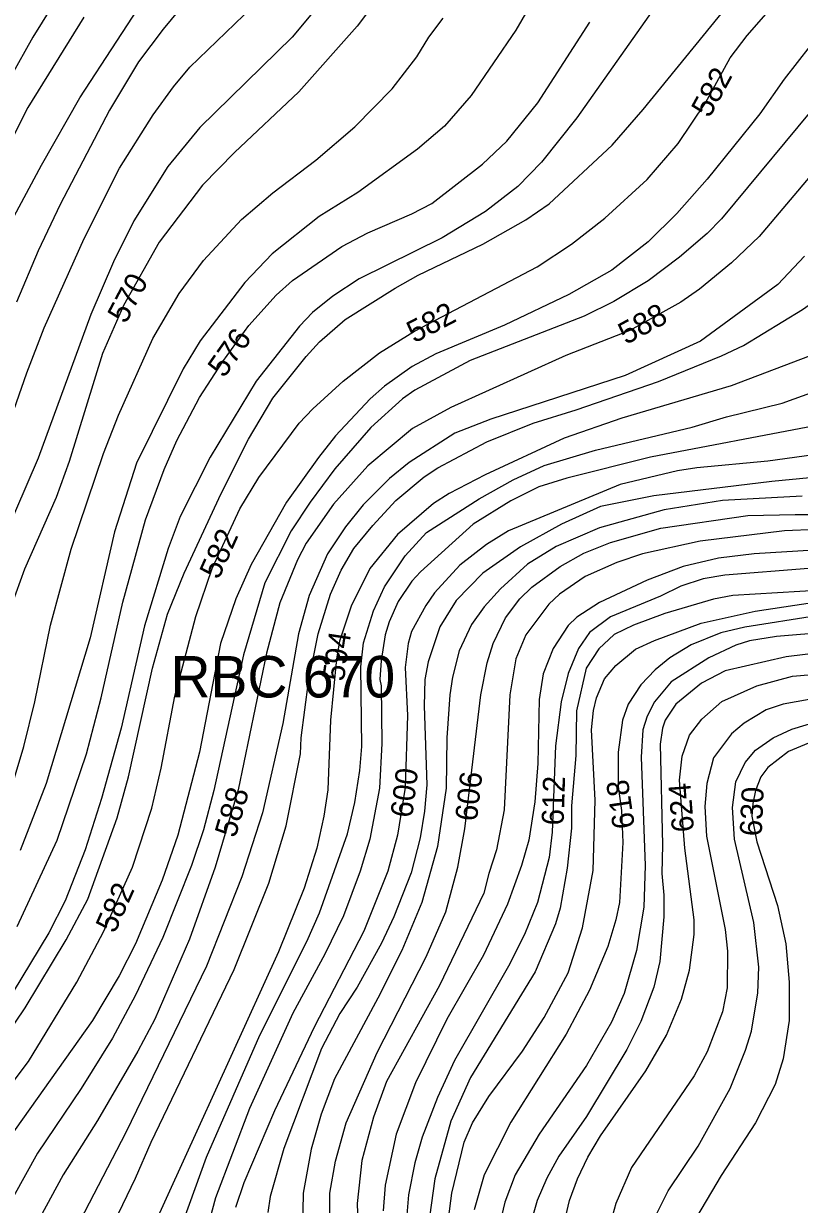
# Model space of a CAD drawing. Extents: x -709418 to -703832, y -1161719 to -1157826.
# Drawn here: x -709000.3 to -708719.1, y -1160771.9 to -1160344.3 of the extents above; entities that cross this region are included whole.
import ezdxf

# ---------------------------------------------------------------- set-up
doc = ezdxf.new("R2010")
doc.units = 0
for name, color, linetype in [('120_vrstevnice hlavní', 7, 'Continuous'), ('121_vrstevnice hlavní_popis', 7, 'Continuous'), ('122_vrstevnice základní', 7, 'Continuous'), ('605_RBC_návrh_popis', 7, 'Continuous')]:
    doc.layers.add(name, color=color, linetype=linetype)

msp = doc.modelspace()

# ---------------------------------------------------------------- linework, layer by layer
at = {"layer": '120_vrstevnice hlavní'}
for points in [[(-708869.72, -1160332.34), (-708879.41, -1160345.21), (-708900.53, -1160369.08), (-708923.82, -1160391.06), (-708935.39, -1160402.78), (-708951.15, -1160423.46), (-708964.03, -1160446.46), (-708971.69, -1160463.82), (-708983.7, -1160502.87), (-708988.47, -1160515.89), (-708999.9, -1160541.93), (-709004.67, -1160554.95)], [(-708953.61, -1160577.8), (-708948.11, -1160558.13), (-708942.04, -1160543.37), (-708928.73, -1160514.45), (-708918.75, -1160494.77), (-708909.93, -1160480.02), (-708897.92, -1160464.83), (-708893.01, -1160459.62), (-708883.75, -1160451.53), (-708865.67, -1160440.1), (-708857.28, -1160435.47), (-708833.85, -1160424.19), (-708818.22, -1160415.36), (-708809.84, -1160409.58), (-708786.98, -1160388.31), (-708775.7, -1160375.44), (-708744.89, -1160337.55)], [(-708978.49, -1160342.03), (-708998.74, -1160374.72), (-709009.3, -1160395.55)], [(-708717.26, -1160428.53), (-708726.95, -1160438.8), (-708755.02, -1160459.33), (-708782.24, -1160471.81), (-708830.95, -1160487.54), (-708843.97, -1160492.6), (-708860.6, -1160503.31), (-708867.69, -1160509.09), (-708877.24, -1160518.64), (-708883.6, -1160526.59), (-708890.11, -1160536.29), (-708896.77, -1160551.47), (-708900.67, -1160565.36), (-708906.31, -1160597.76), (-708913.69, -1160630.16), (-708921.21, -1160653.3), (-708933.94, -1160685.7), (-708963.16, -1160745.88), (-708984.85, -1160787.53)], [(-708704.24, -1160499.11), (-708730.57, -1160502.73), (-708756.32, -1160505.19), (-708763.26, -1160506.34), (-708784.09, -1160511.26), (-708824.59, -1160528.04), (-708832.54, -1160532.96), (-708842.23, -1160540.48), (-708851.35, -1160550.46), (-708854.53, -1160555.09), (-708859.74, -1160564.49), (-708860.9, -1160568.83), (-708862.05, -1160577.51), (-708861.18, -1160594.87), (-708862.05, -1160620.9), (-708864.8, -1160638.26), (-708868.27, -1160651.28), (-708876.95, -1160672.98), (-708895.03, -1160707.69), (-708909.35, -1160738.07), (-708920.49, -1160764.1), (-708923.53, -1160773.07)], [(-708440.12, -1160521.68), (-708459.8, -1160526.16), (-708478.31, -1160531.95), (-708502.32, -1160538.31), (-708531.83, -1160547.14), (-708566.25, -1160555.09), (-708587.93, -1160558.27), (-708616.59, -1160561.6), (-708630.48, -1160561.6), (-708658.54, -1160563.19), (-708688.05, -1160563.05), (-708727.39, -1160566.23), (-708737.22, -1160567.82), (-708742.14, -1160569.41), (-708751.98, -1160574.04), (-708765.57, -1160582.72)], [(-708713.79, -1160534.98), (-708735.49, -1160536.29), (-708748.51, -1160537.88), (-708761.23, -1160540.92), (-708774.25, -1160545.83), (-708791.61, -1160553.93), (-708799.85, -1160559.29), (-708802.89, -1160562.32), (-708808.39, -1160570.57), (-708812.01, -1160579.82), (-708813.45, -1160589.08), (-708813.89, -1160612.23), (-708815.04, -1160626.11), (-708817.21, -1160640), (-708819.82, -1160649.25), (-708824.88, -1160663.14), (-708833.56, -1160681.65), (-708846.86, -1160704.8), (-708858.29, -1160727.94), (-708865.23, -1160746.46), (-708869.28, -1160764.97), (-708870.01, -1160774.23)], [(-709026.37, -1160740.09), (-708999.75, -1160700.75), (-708984.85, -1160676.16), (-708977.04, -1160661.4), (-708966.34, -1160631.9), (-708962.29, -1160617.14), (-708953.61, -1160577.8)], [(-708765.57, -1160582.72), (-708771.65, -1160589.95), (-708774.25, -1160595.16), (-708775.84, -1160600.07), (-708776.42, -1160609.91), (-708774.98, -1160649.25), (-708775.56, -1160664.3), (-708778.16, -1160679.92), (-708782.64, -1160695.54), (-708787.27, -1160705.96), (-708796.24, -1160721.58), (-708813.45, -1160746.46), (-708822.13, -1160761.21), (-708825.89, -1160771.05), (-708829.36, -1160785.8)], [(-708579.35, -1160597.77), (-708623.24, -1160599.35), (-708701.35, -1160601.81), (-708714.37, -1160604.27), (-708723.05, -1160607.89), (-708730.57, -1160613.67), (-708733.17, -1160617.14), (-708735.05, -1160622.06), (-708736.07, -1160626.69), (-708736.36, -1160631.32), (-708734.62, -1160640.57), (-708727.1, -1160663.72), (-708724.06, -1160677.6), (-708722.9, -1160691.49), (-708722.9, -1160705.38), (-708725.07, -1160719.26), (-708727.97, -1160728.52), (-708735.05, -1160742.41), (-708747.49, -1160761.5), (-708756.46, -1160776.54)]]:
    msp.add_lwpolyline(points, dxfattribs=at)
at = {"layer": '122_vrstevnice základní'}
for points in [[(-708791.61, -1160294.44), (-708821.84, -1160346.66), (-708838.04, -1160370.38), (-708847.73, -1160381.52), (-708857.57, -1160389.76), (-708879.12, -1160405.53), (-708893.15, -1160414.21), (-708910.22, -1160427.66), (-708920.05, -1160438.07), (-708936.26, -1160459.19), (-708942.47, -1160469.32), (-708959.4, -1160503.45), (-708967.35, -1160528.33), (-708976.18, -1160566.81), (-708992.09, -1160619.46), (-709001.49, -1160643.76)], [(-708925.98, -1160317.58), (-708949.71, -1160346.37), (-708958.67, -1160358.23), (-708969.09, -1160375.73), (-708987.03, -1160409.87), (-708994.98, -1160426.65), (-709002.79, -1160445.16)], [(-708979.36, -1160321.06), (-708996.86, -1160349.26), (-709013.21, -1160378.19)], [(-709010.31, -1160735.75), (-708998.45, -1160720.13), (-708980.95, -1160691.49), (-708971.26, -1160673.27), (-708960.84, -1160649.83), (-708953.76, -1160628.43), (-708950.43, -1160613.96), (-708945.51, -1160587.93), (-708937.85, -1160559), (-708931.92, -1160541.64), (-708921.89, -1160520.04), (-708914.99, -1160508.66), (-708900.38, -1160488.99), (-708895.47, -1160483.78), (-708884.47, -1160473.8), (-708871.31, -1160463.53), (-708858.58, -1160455.72), (-708814.18, -1160432.43), (-708801.73, -1160424.19), (-708789.59, -1160414.79), (-708774.25, -1160400.75), (-708763.11, -1160387.74), (-708753.14, -1160372.98), (-708744.17, -1160356.78), (-708738.09, -1160348.68), (-708720.16, -1160328.14)], [(-708766.44, -1160331.18), (-708799.85, -1160378.48), (-708812.58, -1160394.54), (-708821.12, -1160403.36), (-708832.83, -1160412.33), (-708848.6, -1160421.87), (-708878.69, -1160436.77), (-708888.23, -1160442.99), (-708895.61, -1160448.92), (-708900.24, -1160453.84), (-708916, -1160473.8), (-708932.64, -1160501.28), (-708943.49, -1160522.83), (-708947.83, -1160534.41), (-708956.51, -1160562.47), (-708964.89, -1160599.5), (-708971.98, -1160624.95), (-708977.91, -1160643.47), (-708985.14, -1160661.98), (-708991.07, -1160673.55), (-709007.56, -1160700.75)], [(-709003.66, -1160414.06), (-708993.82, -1160395.55), (-708979.94, -1160371.25), (-708953.03, -1160330.02)], [(-708885.2, -1160542.22), (-708880.57, -1160534.41), (-708873.77, -1160526.02), (-708865.38, -1160517.05), (-708855.11, -1160508.51), (-708850.19, -1160505.19), (-708832.4, -1160495.79), (-708815.62, -1160488.99), (-708800, -1160484.21), (-708770.2, -1160473.95), (-708747.35, -1160464.69), (-708739.39, -1160460.93), (-708717.99, -1160447.91), (-708709.16, -1160441.69), (-708692.96, -1160428.53), (-708685.44, -1160420.86), (-708673.72, -1160407.26), (-708653.91, -1160386.44), (-708626.14, -1160363.15), (-708604.59, -1160348.25), (-708576.81, -1160332.05)], [(-709021.74, -1160535.56), (-708999.03, -1160470.76), (-708992.81, -1160454.56), (-708978.35, -1160422.16), (-708965.47, -1160396.71), (-708953.32, -1160377.32), (-708945.95, -1160367.2), (-708940.02, -1160360.11), (-708913.98, -1160334.94)], [(-708889.39, -1160332.92), (-708902.99, -1160349.26), (-708936.4, -1160381.95), (-708947.97, -1160396.13), (-708960.27, -1160415.8), (-708967.64, -1160430.55), (-708975.89, -1160449.65), (-708994.98, -1160501.72), (-709007.28, -1160530.36)], [(-709005.68, -1160624.66), (-709000.19, -1160606.15), (-708996.14, -1160589.95), (-708990.5, -1160562.18), (-708982.97, -1160534.7), (-708971.26, -1160499.98), (-708965.91, -1160486.09), (-708953.47, -1160458.32), (-708943.92, -1160442.12), (-708935.1, -1160430.12), (-708921.36, -1160415.22), (-708909.93, -1160405.67), (-708894.31, -1160393.81), (-708880.28, -1160381.66), (-708866.68, -1160367.92), (-708857.71, -1160356.35), (-708853.37, -1160349.26), (-708848.17, -1160342.32)], [(-709002.65, -1160671.24), (-708988.04, -1160640), (-708977.48, -1160608.75), (-708972.13, -1160588.5), (-708964.32, -1160553.79), (-708956.07, -1160523.99), (-708949.27, -1160505.77), (-708944.79, -1160495.35), (-708936.54, -1160479.73), (-708928.01, -1160466.71), (-708918.61, -1160453.7), (-708908.77, -1160442.7), (-708902.84, -1160437.35), (-708884.91, -1160425.06), (-708875.5, -1160420.14), (-708859.59, -1160413.19), (-708852.36, -1160409.43), (-708833.99, -1160395.26), (-708825.17, -1160386.87), (-708813.89, -1160372.98), (-708795.08, -1160343.77)], [(-708715.24, -1160352.44), (-708724.64, -1160364.45), (-708733.46, -1160377.03), (-708752.56, -1160400.61), (-708763.55, -1160413.05), (-708773.96, -1160423.32), (-708787.12, -1160433.6), (-708802.75, -1160442.41), (-708826.04, -1160453.55), (-708850.91, -1160463.96), (-708859.45, -1160468.45), (-708869.43, -1160475.68), (-708874.64, -1160480.16), (-708887.22, -1160493.62), (-708893.44, -1160501.43), (-708905.01, -1160517.63), (-708917.74, -1160540.19), (-708923.38, -1160552.63), (-708928.88, -1160568.83), (-708936.54, -1160608.18), (-708944.35, -1160638.26), (-708949.99, -1160654.46), (-708959.69, -1160677.6), (-708965.62, -1160689.18), (-708975.31, -1160705.38), (-709010.75, -1160755.13)], [(-708710.32, -1160370.38), (-708747.35, -1160415.07), (-708752.54, -1160420.37), (-708762.62, -1160428.93), (-708773.96, -1160437.49), (-708786.4, -1160445.02), (-708797.11, -1160450.22), (-708838.47, -1160466.28), (-708858.44, -1160477.13), (-708862.92, -1160480.17), (-708874.49, -1160490.58), (-708887.51, -1160505.62), (-708896.48, -1160517.63), (-708903.28, -1160528.04), (-708912.82, -1160546.85), (-708920.63, -1160572.88), (-708931.34, -1160622.06), (-708935.1, -1160636.24), (-708939.44, -1160649.25), (-708949.85, -1160675.29), (-708959.69, -1160696.12), (-708968.08, -1160711.74), (-708979.36, -1160729.97), (-708995.27, -1160753.4), (-709003.95, -1160769.02)], [(-708692.82, -1160372.98), (-708733.75, -1160421.44), (-708743.73, -1160430.99), (-708755.3, -1160440.53), (-708762.1, -1160445.16), (-708780.62, -1160455.43), (-708803.76, -1160464.54), (-708845.42, -1160483.35), (-708859.3, -1160491.01), (-708875.5, -1160504.47), (-708887.94, -1160518.35), (-708897.92, -1160532.53), (-708900.96, -1160538.46), (-708907.47, -1160554.08), (-708912.24, -1160572.3), (-708922.51, -1160621.77), (-708930.9, -1160649.83), (-708940.16, -1160675.87), (-708952.74, -1160704.8), (-708958.82, -1160716.37), (-708973.43, -1160741.54), (-708985.87, -1160761.21), (-708994.4, -1160776.83)], [(-708709.16, -1160462.37), (-708743.88, -1160475.54), (-708783.51, -1160487.25), (-708804.34, -1160494.48), (-708832.98, -1160507.79), (-708846, -1160514.45), (-708851.78, -1160518.06), (-708864.8, -1160529.34), (-708874.78, -1160541.64), (-708881.58, -1160555.24), (-708885.77, -1160567.96), (-708886.93, -1160574.33), (-708889.1, -1160596.6), (-708889.97, -1160621.77), (-708891.42, -1160631.32), (-708894.02, -1160642.89), (-708898.65, -1160657.35), (-708907.9, -1160680.5), (-708959.69, -1160794.19)], [(-708877.67, -1160606.15), (-708878.11, -1160577.22), (-708877.1, -1160568.54), (-708873.48, -1160556.97), (-708869.43, -1160548.29), (-708862.05, -1160537.01), (-708854.24, -1160528.62), (-708835.15, -1160516.47), (-708822.85, -1160509.53), (-708811.57, -1160504.32), (-708793.06, -1160498.82), (-708758.05, -1160490.43), (-708745.61, -1160486.67), (-708725.36, -1160481.76), (-708691.52, -1160469.6)], [(-708713.5, -1160490), (-708773.1, -1160501.28), (-708803.47, -1160508.95), (-708813.6, -1160512.13), (-708823.72, -1160517.19), (-708837.32, -1160525.58), (-708856.41, -1160542.8), (-708859.59, -1160546.27), (-708864.51, -1160553.64), (-708867.84, -1160561.02), (-708869.28, -1160565.65), (-708870.73, -1160574.91), (-708871.17, -1160581.85), (-708870.73, -1160584.16), (-708870.44, -1160604.99), (-708871.31, -1160621.19), (-708874.78, -1160639.71), (-708878.25, -1160651.28), (-708884.33, -1160667.48), (-708891.13, -1160681.36), (-708902.7, -1160702.63), (-708918.46, -1160737.2), (-708930.76, -1160769.6), (-708934.52, -1160783.48)], [(-708435.5, -1160492.6), (-708478.89, -1160508.66), (-708495.67, -1160516.47), (-708514.33, -1160523.41), (-708541.67, -1160530.94), (-708556.13, -1160533.54), (-708564.52, -1160536.14), (-708585.35, -1160540.34), (-708623.53, -1160545.98), (-708670.4, -1160547.14), (-708743.3, -1160551.47), (-708750.24, -1160552.78), (-708767.89, -1160557.98), (-708779.23, -1160562.14), (-708786.29, -1160565.57), (-708791.84, -1160570.71), (-708796.37, -1160577.8), (-708799.9, -1160593.21), (-708800.14, -1160609.33), (-708801.73, -1160627.56), (-708801.73, -1160635.66), (-708803.33, -1160650.12), (-708805.79, -1160664.59)], [(-708691.52, -1160506.49), (-708729.12, -1160510.11), (-708771.94, -1160515.31), (-708791.23, -1160519.22), (-708805.35, -1160525.58), (-708820.25, -1160533.83), (-708833.85, -1160543.37), (-708843.54, -1160553.21), (-708849.47, -1160562.76), (-708853.66, -1160575.49), (-708854.82, -1160581.85), (-708855.11, -1160591.4), (-708854.1, -1160620.04), (-708854.96, -1160629.58), (-708856.56, -1160639.13), (-708859.88, -1160651.86), (-708866.1, -1160667.77), (-708870.59, -1160677.31), (-708879.41, -1160693.23), (-708885.63, -1160702.77), (-708892.28, -1160715.5), (-708906.02, -1160751.66), (-708910.94, -1160769.02), (-708911.81, -1160774.81)], [(-708718.13, -1160515.46), (-708747.06, -1160517.05), (-708768.18, -1160520.38), (-708791.61, -1160526.89), (-708807.23, -1160533.68), (-708817.65, -1160540.05), (-708827.48, -1160549.02), (-708833.41, -1160555.52), (-708837.9, -1160561.89), (-708842.38, -1160571.44), (-708844.84, -1160580.98), (-708845.85, -1160587.35), (-708846.86, -1160602.97), (-708847.15, -1160621.19), (-708850.34, -1160642.31), (-708855.98, -1160662.56), (-708863.21, -1160679.92), (-708871.89, -1160697.28), (-708887.65, -1160726.49), (-708892.43, -1160739.22), (-708896.04, -1160751.95), (-708898.94, -1160767.86), (-708899.23, -1160780.59)], [(-708887.22, -1160756.29), (-708883.32, -1160742.41), (-708872.18, -1160716.95), (-708854.39, -1160682.23), (-708847.3, -1160666.03), (-708842.96, -1160649.83), (-708840.35, -1160635.95), (-708834.57, -1160587.35), (-708832.26, -1160575.78), (-708830.09, -1160568.83), (-708825.6, -1160559.57), (-708820.39, -1160552.63), (-708816.06, -1160548.44), (-708805.79, -1160540.92), (-708797.25, -1160536.14), (-708787.56, -1160532.24), (-708769.34, -1160527.03), (-708737.8, -1160522.4), (-708720.73, -1160522.11), (-708693.83, -1160522.11)], [(-708701.06, -1160527.03), (-708724.49, -1160528.04), (-708755.16, -1160531.8), (-708775.99, -1160536.29), (-708785.25, -1160539.47), (-708796.82, -1160544.53), (-708806.08, -1160550.9), (-708809.98, -1160554.51), (-708818.22, -1160565.65), (-708821.84, -1160574.33), (-708824.01, -1160587.35), (-708826.18, -1160629), (-708828.93, -1160643.47), (-708831.68, -1160652.15), (-708833.49, -1160659.27), (-708849.61, -1160692.65), (-708868.71, -1160727.36), (-708873.48, -1160740.38), (-708877.67, -1160756), (-708879.41, -1160771.62), (-708878.83, -1160788.69)], [(-708715.82, -1160541.64), (-708746.19, -1160544.1), (-708754, -1160545.4), (-708762.1, -1160548), (-708769.48, -1160551.62), (-708787.56, -1160559.14), (-708795.23, -1160564.78), (-708799.13, -1160570.57), (-708802.91, -1160579.62), (-708805.43, -1160589.89), (-708807.52, -1160605.86), (-708808.68, -1160637.1), (-708809.84, -1160646.36), (-708814.03, -1160662.56), (-708818.8, -1160674.13), (-708824.59, -1160685.7), (-708844.12, -1160719.84), (-708850.34, -1160733.15), (-708855.83, -1160747.61), (-708858.44, -1160756.87), (-708860.75, -1160768.44), (-708861.76, -1160780.01)], [(-708973.43, -1160791.01), (-708959.69, -1160762.37), (-708954.05, -1160749.35), (-708923.96, -1160686.86), (-708911.38, -1160655.62), (-708905.16, -1160634.79), (-708899.95, -1160608.75), (-708899.66, -1160602.97), (-708897.06, -1160582.72), (-708893.58, -1160565.36), (-708889.1, -1160550.9), (-708885.2, -1160542.22)], [(-708846.29, -1160777.12), (-708845.13, -1160767.86), (-708840.65, -1160749.35), (-708837.61, -1160742.41), (-708831.68, -1160732.86), (-708819.53, -1160716.37), (-708811.57, -1160704.22), (-708802.89, -1160688.02), (-708797.69, -1160671.82), (-708793.92, -1160650.99), (-708793.2, -1160625.53), (-708794.5, -1160600.07), (-708793.78, -1160593.13), (-708792.62, -1160588.5), (-708789.73, -1160581.56), (-708785.68, -1160576.79), (-708778.59, -1160570.86), (-708771.65, -1160567.67), (-708754.73, -1160561.45), (-708735.2, -1160557.11), (-708714.37, -1160553.93)], [(-708712.92, -1160558.85), (-708738.96, -1160562.9), (-708747.64, -1160564.93), (-708758.34, -1160569.27), (-708766.15, -1160574.04), (-708771.36, -1160578.38), (-708776.57, -1160583.73), (-708781.2, -1160590.82), (-708783.22, -1160596.6), (-708784.81, -1160608.18), (-708784.81, -1160620.61), (-708783.66, -1160629.29), (-708783.08, -1160640.86), (-708784.38, -1160662.56), (-708785.68, -1160668.93), (-708788.57, -1160678.47), (-708795.23, -1160694.38), (-708803.62, -1160710.29), (-708823.72, -1160742.12), (-708833.41, -1160761.21)], [(-708546.1, -1160561.18), (-708587.37, -1160566.66), (-708636.55, -1160569.7), (-708711.19, -1160572.01), (-708723.92, -1160573.6), (-708746.06, -1160578.74), (-708754.64, -1160583.15), (-708763.96, -1160590.73), (-708767.74, -1160596.6), (-708768.76, -1160599.5), (-708769.62, -1160605.28), (-708768.76, -1160641.73), (-708769.05, -1160652.15), (-708768.32, -1160659.96), (-708768.32, -1160667.77), (-708769.77, -1160683.97), (-708771.94, -1160693.23), (-708776.57, -1160705.67), (-708781.63, -1160715.79), (-708796.24, -1160740.09), (-708806.36, -1160754.41), (-708810.7, -1160762.37), (-708814.18, -1160770.47), (-708817.07, -1160780.59)], [(-708805.5, -1160783.48), (-708802.46, -1160770.47), (-708799.57, -1160762.66), (-708795.8, -1160754.84), (-708791.18, -1160747.03), (-708774.83, -1160723.6), (-708767.31, -1160710.58), (-708761.81, -1160697.56), (-708758.92, -1160687.15), (-708757.33, -1160674.13), (-708757.33, -1160668.93), (-708760.66, -1160642.89), (-708762.54, -1160618.3), (-708761.67, -1160609.62), (-708758.92, -1160601.96), (-708754.52, -1160596.18), (-708747.21, -1160589.82), (-708734.62, -1160584.16), (-708721.6, -1160580.69), (-708705.98, -1160579.25)], [(-708579.35, -1160582.72), (-708603.57, -1160584.6), (-708656.22, -1160587.2), (-708694.7, -1160587.06), (-708710.9, -1160588.21), (-708725.07, -1160590.82), (-708731.15, -1160592.84), (-708739.1, -1160597.61), (-708743.73, -1160601.52), (-708750.22, -1160610.21), (-708752.74, -1160619.5), (-708753.42, -1160627.85), (-708752.85, -1160638.55), (-708746.05, -1160672.4), (-708745.18, -1160680.21), (-708745.32, -1160693.52), (-708747.06, -1160702.19), (-708752.56, -1160716.66), (-708757.33, -1160725.34), (-708780.04, -1160758.6), (-708785.68, -1160771.62), (-708789.3, -1160784.64)], [(-708772.52, -1160778.57), (-708766.73, -1160766.99), (-708755.88, -1160750.79), (-708744.17, -1160729.97), (-708738.67, -1160716.08), (-708736.5, -1160709.14), (-708734.19, -1160695.25), (-708733.9, -1160685.99), (-708735.63, -1160669.79), (-708742.72, -1160639.71), (-708743.44, -1160628.14), (-708742.14, -1160618.88), (-708738.82, -1160611.94), (-708735.05, -1160607.45), (-708728.69, -1160602.97), (-708721.89, -1160599.79), (-708711.48, -1160596.75), (-708693.25, -1160594.43), (-708652.75, -1160595.45), (-708613.7, -1160593.42), (-708578.6, -1160590.62)], [(-708948.39, -1160794.49), (-708933.94, -1160754.84), (-708914.7, -1160710.58), (-708897.63, -1160676.74), (-708893.01, -1160666.32), (-708882.88, -1160637.68), (-708880.28, -1160626.4), (-708878.4, -1160614.83), (-708877.67, -1160606.15)], [(-708805.79, -1160664.59), (-708807.52, -1160670.37), (-708814.9, -1160687.73), (-708838.33, -1160725.92), (-708845.42, -1160741.83), (-708851.2, -1160762.66), (-708853.81, -1160780.88)], [(-708889.39, -1160784.06), (-708889.24, -1160767.86), (-708887.22, -1160756.29)], [(-708833.41, -1160761.21), (-708837.03, -1160773.94)]]:
    msp.add_lwpolyline(points, dxfattribs=at)

# ---------------------------------------------------------------- texts
at = {"layer": '121_vrstevnice hlavní_popis'}
for s, rotation, p in [('582', 61.3645, (-708751.74, -1160378.81)), ('570', 61.9591, (-708963.25, -1160453.35)), ('582', 27.5958, (-708858.71, -1160460.2)), ('588', 28.4724, (-708781.98, -1160460.76)), ('576', 54.8434, (-708927.6, -1160472.95)), ('582', 65.765, (-708929.59, -1160545.96)), ('594', 81.4789, (-708884.21, -1160582.76)), ('600', 82.829, (-708859.47, -1160632.18)), ('606', 83.3228, (-708836.03, -1160633.43)), ('612', 88.1803, (-708804.59, -1160634.77)), ('618', 98.4421, (-708778.71, -1160635.33)), ('588', 73.5426, (-708923.53, -1160639.48)), ('624', 94.4662, (-708757.28, -1160636.83)), ('630', 87.4624, (-708732.81, -1160638.72)), ('582', 65.8144, (-708967.2, -1160674.09))]:
    msp.add_text(s, height=8, rotation=rotation, dxfattribs=at).set_placement(p)
at = {"layer": '605_RBC_návrh_popis'}
msp.add_text('RBC 670', height=15, dxfattribs=at).set_placement((-708947.02, -1160588.35))

doc.saveas('drawing.dxf')
